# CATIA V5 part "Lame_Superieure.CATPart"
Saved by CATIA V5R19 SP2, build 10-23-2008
Part number: Lame_Superieure
Bounding box of the stored display mesh (mm): x 0 to 1, y -50.918 to 3.815, z -4.489 to 6.629
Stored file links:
  G:\EU_thinkMotion\CFAO_2010\MMS_groupe3\MMS_groupe3\A reprendre\lletoffe\lletoffe_Thinkmotion_CFAO\Modèle Catia\Lame_Superieure.CATPart
  E:\CFAO\Last Catia\Lame superieure.CATPart
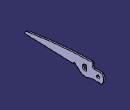
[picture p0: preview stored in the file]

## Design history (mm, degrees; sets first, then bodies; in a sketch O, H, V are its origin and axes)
Parameters
  Epaisseur = 1 mm
  Longueur_lame = 35 mm
Set1
  Point1: (0, 0, 0)
  Point2: (0, -9, 1)
  Point3: (1, -9, 1)
  Point4: (1, 0, 0)
  Line1: type PtPt, FirstPoint Point1, SecondPoint Point4, Start 10, End 10
  Line2: type PtPt, FirstPoint Point2, SecondPoint Point3, Start 10, End 10
  Plane1: type Offset, RefPlane yz-plane, Offset 1 {= Epaisseur}
  Sketch1 on yz-plane, origin (0, 0, 0), H (0, 1, 0), V (0, 0, 1)
    circle A1 centre (0, 0) radius 1
    arc A2 centre (0, 0) radius 4 from (2.3632, -3.2273) to (2.4, 3.2) ccw
    construction line L1 through (-13.3999, 0) direction (1, 0)
    line L2 (-2.9685, 3.25) -> (2.25, 3.25)
    arc A3 centre (-9, 1) radius 2 from (-8, 2.7321) to (-8, -0.7321) ccw
    arc A4 centre (-9, 1) radius 5.5 from (-13.558, -2.0781) to (-5.9786, -3.5958) ccw
    arc A5 centre (-2.9685, 4.25) radius 1 from (-3.9679, 4.2849) to (-2.9685, 3.25) ccw
    line L3 (-3.9041, 6.1114) -> (-3.9679, 4.2849)
    arc A6 centre (-4.4038, 6.1288) radius 0.5 from (-3.9041, 6.1114) to (-4.4136, 6.6287) ccw
    arc A7 centre (-4.3306, -6.1026) radius 3 from (-4.2259, -3.1044) to (-5.9786, -3.5958) ccw
    construction line L4 through (0, 24.9344) direction (0, 1)
    point P1 (0, 3.25)
    point P2 (0, -3.25)
    point P3 (-9, 1)
    arc A8 centre (-16.0442, -3.7571) radius 3 from (-13.558, -2.0781) to (-15.9395, -0.7589) ccw
    point P4 (-48.9194, 0.3928)
    arc A9 centre (-48.9194, 0.3928) radius 2 from (-49.2577, 2.364) to (-50.9182, 0.4626) ccw
    arc A10 centre (1.4867, -293.3132) radius 300 from (-4.4136, 6.6287) to (-49.2577, 2.364) ccw
    point P5 (-4.3306, -6.1026)
    line L5 (-8, 2.7321) -> (-8, -0.7321)
    point P6 (0, 0)
    line L6 (2.0503, -3.3236) -> (-4.2259, -3.1044)
    arc A11 centre (2.0678, -2.8239) radius 0.5 from (2.0503, -3.3236) to (2.3632, -3.2273) ccw
    arc A12 centre (2.25, 3) radius 0.25 from (2.4, 3.2) to (2.25, 3.25) ccw
    point P13 (-16.0442, -3.7571)
    point P14 (-15.9395, -0.7589)
    axis line L7 (-15.9395, -0.7589) -> (-50.9182, 0.4626)
    line L8 (-50.9182, 0.4626) -> (-16.9389, -0.724)
    line L9 (-16.9389, -0.724) -> (-16.904, 0.2754)
    line L10 (-16.904, 0.2754) -> (-15.9046, 0.2405)
    line L11 (-15.9046, 0.2405) -> (-15.9395, -0.7589)
    point P36 (-15.9395, -0.7589)
    reference projected point E1 (0, 0) from Line1
    radius A1 = 1
    radius A2 = 4
    radius A3 = 2
    radius A4 = 5.5
    radius A5 = 1
    radius A6 = 0.5
    radius A7 = 3
    distance P3 L1 = 1
    radius A8 = 3
    radius A9 = 2
    radius A10 = 300
    distance P1 P2 = 6.5
    distance L5 P3 = 1
    distance L6 P6 = 3.25
    radius A11 = 0.5
    radius A12 = 0.25
    distance L5 L4 = 8
    angle L6 L1 = 2
    length L7 = 35 {= Longueur_lame}
    distance L10 L8 = 1
    length L10 = 1
    horizontal: L2 L1
    tangency: A5 L2, L3 A5, A6 L3, A4 A7, A8 A4, A10 A9, A6 A10, A10 A4, A11 A2, A11 L6, A12 L2, A12 A2, L6 A7, L7 A3, L8 A8
    coincidence: P1 L4, P1 L2, L3 P5, P36 P14, P13 L11, P4 L8, P6 L4, P6 L1
    symmetry: P2 P1 L1
    perpendicularity: L3 L6, L4 L1, L10 L9, L10 L11, L9 L8
    parallelism: L8 L6
    vertical: L4 V
    concentricity: A1 E1
Body1 (main body)
  Pad1: profile Sketch1, direction (1, 0, 0), up to Plane1
  Chamfer1: length 1, angle 45, on edge [start face of Pad1 | face of Pad1 from Sketch1.L8]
